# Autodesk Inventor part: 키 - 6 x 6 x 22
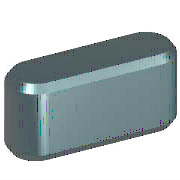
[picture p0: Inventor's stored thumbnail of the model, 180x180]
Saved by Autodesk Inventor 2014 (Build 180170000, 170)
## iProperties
IsCustomPart: 1
Created: 2012-02
Part Number: 키 - 6 x 6 x 22
Material: 강철, 연강
Description: 키 및 해당 키홈
Document SubType Name: Modeling
Standard: KS B 1311
Designer: mduedu
Standards Organization: KS
Language: ko-KR
Size Designation: 6 x 6 x 22
Categories: <MemberInstance><Categories><Category DisplayName="샤프트 부품" InternalName="7f7aeb1f-a693-4053-b835-cee3144e0d98" Mnemonic="SHFT"><Category DisplayName="키" Interna
Density: 7.86 g/cm^3
Mass: 5.79788 g
Surface Area: 5.294 cm^2
Volume: 0.737644 cm^3
Appearance: 노란색
Author: mduedu
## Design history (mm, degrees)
workplane "Work Plane1"
workplane "Work Plane2"
sketch "스케치1"
  geometry: L1 (3, 3)-(19, 3); L2 (19, -3)-(3, -3); L3 (0, 9.4)-(0, -7.4) reference; L4 (-5, 0)-(30, 0) reference; L5 (22, 0)-(22, 7); A1 r 3 centre (3, 0) between (3, 3) and (3, -3); A2 r 3 centre (19, 0) between (19, -3) and (19, 3)
  constraints: 6 end point, 5 point on circle, 4 tangent, 3 point on line, 2 centre point, 1 horizontal, 1 parallel, 1 perpendicular
  dimensions: "d0" = 3 radius of A1 (= 0.5 x PB); "d13" = 3 radius of A2 (= 0.5 x PB); "d14" = 22 distance between parallel lines of L5 L3 (= NLG)
extrude "본체1" new body sketch "스케치1" taper "d3" = 0 deg; stored distance "d4" = 10
workplane "Work Plane3"
body "Solid1"
chamfer "모따기1" distance "d8" = 0.4 (= PHH); stored, may be unused: second distance "d9" = 0.4 (= PHH), angle "d15" = 45 deg
other parameters: "d1" = -3.5 (= -PNT), "d2" = 2.5 (= PH - PNT), "NLG" = 22 [user parameter; used in 3 equation terms], "PB" = 6 [user parameter; used in 2 equation terms], "PNT" = 3.5 [user parameter; used in 2 equation terms], "PH" = 6 [user parameter; used in 1 equation term], "PHH" = 0.4 [user parameter; used in 2 equation terms], "d10" = 0, "d16" = 0, "d17" = 0, "d18" = 0, "WDMIN" = 17 [user parameter], "PLB2" = 22 (= NLG) [user parameter], "WDMAX" = 22 [user parameter], "PLB1" = 22 (= NLG) [user parameter], "RR" = 0.16 [user parameter], "PUEB" = 2.8 [user parameter]
